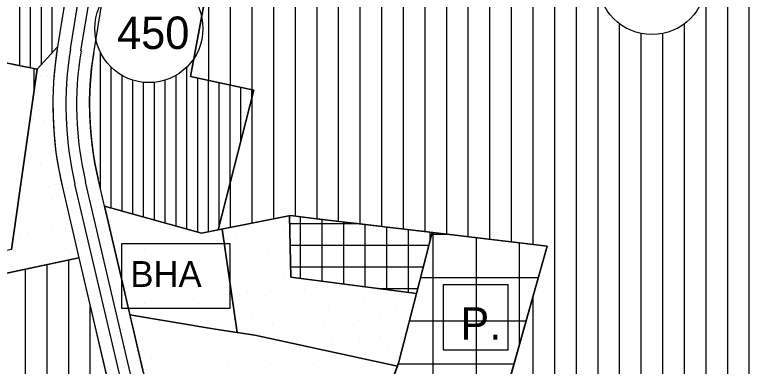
# Model space of a CAD drawing. Extents: x 419109 to 421295, y 4452223 to 4457798.
# Drawn here: x 420565 to 420904.9, y 4454003.1 to 4454165.8 of the extents above; entities that cross this region are included whole.
import ezdxf

# ---------------------------------------------------------------- set-up
doc = ezdxf.new("R2010")
doc.units = 0
for name, color, linetype in [('ADA', 7, 'Continuous'), ('ADAKENARI', 7, 'Continuous'), ('Default', 7, 'Continuous'), ('KALDIRIM', 7, 'Continuous'), ('LJ_SEMBOL', 7, 'Continuous'), ('PL_AYA_PARK_DINLENME', 7, 'Continuous'), ('PL_K_BHA', 7, 'Continuous'), ('PL_K_PAZAR_ALANI', 7, 'Continuous'), ('PL_K_TALI_IS_MRK', 7, 'Continuous'), ('PL_KON_MEV_350', 7, 'Continuous'), ('PL_KON_MEV_450', 7, 'Continuous'), ('PL_OZEL_DONATI', 7, 'Continuous'), ('SM_DAIRE', 7, 'Continuous'), ('SM_TAKS', 7, 'Continuous'), ('TR_ORTAYOGUNKONUT', 7, 'Continuous'), ('TR_PARKALANI', 7, 'Continuous'), ('TR_PAZARLAMAAL', 7, 'Continuous'), ('TR_SAGLIKTESIS', 7, 'Continuous'), ('TR_TALIISMERK', 7, 'Continuous'), ('TR_YONETIMMERK', 7, 'Continuous'), ('TR_YUKSEKYOGUNKONUT', 7, 'Continuous')]:
    doc.layers.add(name, color=color, linetype=linetype)

# ---------------------------------------------------------------- blocks, each defined once
blk = doc.blocks.new('POINT_DISPLAY')
at = {"layer": 'Default'}
blk.add_line((0, 0), (0, 0), dxfattribs=at)

msp = doc.modelspace()

# ---------------------------------------------------------------- linework, layer by layer
at = {"layer": 'ADA'}
for p, q in [((420646.34, 4454137.24), (420659.27, 4454206.63)), ((420575.43, 4454140.51), (420584.82, 4454150.89)), ((420575.43, 4454140.51), (420552.34, 4454145.16)), ((420575.43, 4454140.51), (420563.47, 4454057.09)), ((420675.69, 4454130.86), (420646.34, 4454137.24)), ((420659.2, 4454066.25), (420675.69, 4454130.86)), ((420606.57, 4454077.19), (420651.48, 4454064.74)), ((420659.2, 4454066.25), (420692.66, 4454072.81)), ((420692.66, 4454072.81), (420704.57, 4454071.4)), ((420704.57, 4454071.4), (420761.09, 4454064.67)), ((420651.48, 4454064.74), (420659.2, 4454066.25)), ((420667.91, 4454018.78), (420660.92, 4454066.59)), ((420750.88, 4454036.79), (420758.11, 4454065.02)), ((420761.09, 4454064.67), (420811.35, 4454058.68)), ((420811.35, 4454058.68), (420787.88, 4453975.61)), ((420449.98, 4454022.67), (420594.69, 4454053.33))]:
    msp.add_line(p, q, dxfattribs=at)
for points in [[(420750.88, 4454036.79), (420692.77, 4454044.43), (420692.08, 4454072.7)], [(420742.08, 4454003.26), (420742.77, 4454005.15), (420750.88, 4454036.79)], [(420742.08, 4454003.26), (420676.14, 4454017.51), (420669.88, 4454018.47), (420657.7, 4454020.34), (420618.32, 4454026.98)], [(420738.6, 4453993.7), (420742.77, 4454005.15)]]:
    msp.add_lwpolyline(points, dxfattribs=at)
at = {"layer": 'ADAKENARI'}
for p, q in [((420623.09, 4454386.03), (420584.82, 4454150.89)), ((420601.6, 4454148.16), (420640.08, 4454384.64)), ((420606.57, 4454077.19), (420603.6, 4454089.87)), ((420587.04, 4454086), (420594.69, 4454053.33)), ((420615.47, 4454039.16), (420606.57, 4454077.19)), ((420594.69, 4454053.33), (420635.91, 4453877.22)), ((420623.71, 4454003.95), (420615.47, 4454039.16)), ((420642.06, 4453925.53), (420623.71, 4454003.95))]:
    msp.add_line(p, q, dxfattribs=at)
for radius in [167, 150]:
    msp.add_arc((420749.65, 4454124.06), radius, 170.7564, 193.1743, dxfattribs=at)
at = {"layer": 'KALDIRIM'}
for p, q in [((420590.74, 4454149.92), (420600.91, 4454212.42)), ((420595.67, 4454149.12), (420605.88, 4454211.86)), ((420619.82, 4453972.32), (420592.89, 4454087.37)), ((420624.73, 4453973.26), (420597.75, 4454088.51))]:
    msp.add_line(p, q, dxfattribs=at)
for radius in [161, 156]:
    msp.add_arc((420749.65, 4454124.06), radius, 170.7564, 193.1743, dxfattribs=at)
at = {"layer": 'LJ_SEMBOL'}
msp.add_lwpolyline([(420614.58, 4454059.92), (420664.58, 4454059.92), (420664.58, 4454029.92), (420614.58, 4454029.92), (420614.58, 4454059.92), (420664.58, 4454059.92)], dxfattribs=at)
msp.add_lwpolyline([(420763.3, 4454010.79), (420793.3, 4454010.79), (420793.3, 4454040.79), (420763.3, 4454040.79)], close=True, dxfattribs=at)
at = {"layer": 'PL_AYA_PARK_DINLENME'}
for points in [[(420563.47, 4454057.09), (420575.43, 4454140.51), (420584.82, 4454150.89), (420584.82, 4454150.89), (420583.7, 4454142.8), (420582.99, 4454134.66), (420582.67, 4454126.5), (420582.75, 4454118.33), (420583.23, 4454110.18), (420584.1, 4454102.06), (420585.38, 4454094), (420587.04, 4454086), (420594.69, 4454053.33), (420449.98, 4454022.67)], [(420742.08, 4454003.26), (420742.77, 4454005.15), (420750.88, 4454036.79), (420692.77, 4454044.43), (420692.08, 4454072.7), (420684.86, 4454071.28), (420674.86, 4454069.32), (420664.86, 4454067.36), (420660.92, 4454066.59), (420667.91, 4454018.78), (420669.88, 4454018.47), (420676.14, 4454017.51), (420742.08, 4454003.26)]]:
    msp.add_lwpolyline(points, dxfattribs=at)
at = {"layer": 'PL_K_BHA'}
msp.add_lwpolyline([(420649.66, 4454065.24), (420644.66, 4454066.63), (420639.66, 4454068.02), (420634.66, 4454069.4), (420629.66, 4454070.79), (420624.66, 4454072.17), (420619.66, 4454073.56), (420614.66, 4454074.95), (420609.66, 4454076.33), (420606.57, 4454077.19), (420615.47, 4454039.16), (420618.32, 4454026.98), (420657.7, 4454020.34), (420667.91, 4454018.78), (420660.92, 4454066.59), (420659.2, 4454066.25), (420654.66, 4454065.37), (420651.48, 4454064.74), (420649.66, 4454065.24)], dxfattribs=at)
at = {"layer": 'PL_K_PAZAR_ALANI'}
msp.add_lwpolyline([(420804.86, 4454059.46), (420794.86, 4454060.65), (420784.86, 4454061.84), (420774.86, 4454063.03), (420764.86, 4454064.22), (420761.09, 4454064.67), (420758.11, 4454065.02), (420750.88, 4454036.79), (420742.77, 4454005.15), (420742.08, 4454003.26), (420738.6, 4453993.7), (420738.02, 4453990.72), (420745.54, 4453988.44), (420755.45, 4453985.44), (420787.88, 4453975.61), (420794.86, 4454000.31), (420804.86, 4454035.71), (420811.35, 4454058.68), (420804.86, 4454059.46)], dxfattribs=at)
at = {"layer": 'PL_K_TALI_IS_MRK'}
msp.add_lwpolyline([(420758.11, 4454065.02), (420754.86, 4454065.41), (420744.86, 4454066.6), (420734.86, 4454067.79), (420724.86, 4454068.98), (420714.86, 4454070.17), (420704.86, 4454071.36), (420704.57, 4454071.4), (420694.86, 4454072.55), (420692.66, 4454072.81), (420692.08, 4454072.7), (420692.77, 4454044.43), (420750.88, 4454036.79), (420758.11, 4454065.02)], dxfattribs=at)
at = {"layer": 'PL_KON_MEV_350'}
for points in [[(420474.73, 4454415.3), (420589.01, 4454400.52), (420552.34, 4454145.16), (420575.43, 4454140.51), (420563.47, 4454057.09), (420525.18, 4454049.57), (420441.81, 4454052.61), (420443.29, 4454073.24), (420452.08, 4454141.13), (420509.8, 4454133.33), (420520.05, 4454189.39), (420424.05, 4454204.21), (420426.46, 4454230.76), (420449.87, 4454228.36), (420493.48, 4454293.72), (420534.29, 4454288.28), (420537.28, 4454311.95), (420497.84, 4454316.84), (420493.48, 4454293.72), (420449.87, 4454228.36)], [(420491, 4453847.88), (420458.18, 4453987.01), (420449.98, 4454022.67), (420594.69, 4454053.33), (420635.91, 4453877.22)]]:
    msp.add_lwpolyline(points, close=True, dxfattribs=at)
msp.add_lwpolyline([(420787.88, 4453975.61), (420811.35, 4454058.68), (420761.09, 4454064.67), (420704.57, 4454071.4), (420692.66, 4454072.81), (420659.2, 4454066.25), (420675.69, 4454130.86), (420646.34, 4454137.24), (420659.27, 4454206.63)], dxfattribs=at)
at = {"layer": 'PL_KON_MEV_450'}
for points in [[(420575.43, 4454140.51), (420552.34, 4454145.16), (420589.01, 4454400.52), (420614.77, 4454397.18), (420623.09, 4454386.03), (420584.82, 4454150.89), (420584.82, 4454150.89)], [(420601.6, 4454148.16), (420640.08, 4454384.64), (420651.68, 4454394.92), (420664.91, 4454395.45), (420634.86, 4454213.81), (420659.27, 4454206.63), (420646.34, 4454137.24), (420675.69, 4454130.86), (420659.2, 4454066.25), (420651.48, 4454064.74), (420606.57, 4454077.19), (420603.6, 4454089.87), (420602.1, 4454097.06), (420600.96, 4454104.3), (420600.17, 4454111.59), (420599.74, 4454118.92), (420599.66, 4454126.25), (420599.95, 4454133.58), (420600.6, 4454140.89)]]:
    msp.add_lwpolyline(points, close=True, dxfattribs=at)
at = {"layer": 'PL_OZEL_DONATI'}
msp.add_lwpolyline([(420618.32, 4454026.98), (420623.71, 4454003.95), (420642.06, 4453925.53), (420642.67, 4453922.94), (420702.7, 4453941.9), (420714.74, 4453945.7), (420713.26, 4453950.4), (420714.55, 4453952.93), (420729.9, 4453957.83), (420732.17, 4453960.39), (420738.02, 4453990.72), (420738.6, 4453993.7), (420742.08, 4454003.26), (420676.14, 4454017.51), (420669.88, 4454018.47), (420667.91, 4454018.78), (420657.7, 4454020.34), (420618.32, 4454026.98)], dxfattribs=at)
at = {"layer": 'SM_DAIRE'}
for centre in [(420859.85, 4454181.58), (420627.09, 4454159.35)]:
    msp.add_circle(centre, 25, dxfattribs=at)
at = {"layer": 'TR_ORTAYOGUNKONUT'}
for p, q in [((420744.86, 4454066.6), (420744.86, 4454398.67)), ((420664.86, 4454133.22), (420664.86, 4454395.11)), ((420734.86, 4454067.79), (420734.86, 4454398.27)), ((420884.86, 4453954.97), (420884.86, 4454392.8)), ((420894.86, 4453952.55), (420894.86, 4454387.56)), ((420904.86, 4453950.13), (420904.86, 4454382.32)), ((420724.86, 4454068.98), (420724.86, 4454277.21)), ((420674.86, 4454069.32), (420674.86, 4454257.68)), ((420684.86, 4454071.28), (420684.86, 4454254.14)), ((420694.86, 4454072.55), (420694.86, 4454250.6)), ((420704.86, 4454071.36), (420704.86, 4454247.06)), ((420714.86, 4454070.17), (420714.86, 4454243.52)), ((420824.86, 4453940.39), (420824.86, 4454243.94)), ((420754.86, 4454065.41), (420754.86, 4454236.99)), ((420764.86, 4454064.22), (420764.86, 4454233.89)), ((420774.86, 4454063.03), (420774.86, 4454230.79)), ((420784.86, 4454061.84), (420784.86, 4454227.69)), ((420814.86, 4453942.58), (420814.86, 4454225.84)), ((420794.86, 4454060.65), (420794.86, 4454224.59)), ((420804.86, 4454059.46), (420804.86, 4454221.49)), ((420654.86, 4454135.39), (420654.86, 4454182.95)), ((420834.86, 4453938.19), (420834.86, 4454180.89)), ((420844.86, 4453936), (420844.86, 4454161.57)), ((420874.86, 4453957.38), (420874.86, 4454161.58)), ((420854.86, 4453961.89), (420854.86, 4454157.08)), ((420864.86, 4453959.8), (420864.86, 4454157.08)), ((420574.05, 4454130.84), (420574.05, 4454140.78)), ((420664.86, 4454067.36), (420664.86, 4454088.42)), ((420589.98, 4453867.92), (420589.98, 4454052.33)), ((420579.98, 4453865.89), (420579.98, 4454050.21)), ((420569.98, 4453863.87), (420569.98, 4454048.09)), ((420804.86, 4453944.78), (420804.86, 4454035.71)), ((420599.98, 4453869.94), (420599.98, 4454030.74))]:
    msp.add_line(p, q, dxfattribs=at)
at = {"layer": 'TR_PAZARLAMAAL'}
for p, q in [((420757.91, 4454064.23), (420764.73, 4454064.23)), ((420758.61, 4453984.48), (420758.61, 4454064.96)), ((420778.61, 4453978.42), (420778.61, 4454062.58)), ((420798.61, 4454013.6), (420798.61, 4454060.2)), ((420752.78, 4454044.23), (420807.26, 4454044.23)), ((420747.66, 4454024.23), (420801.61, 4454024.23)), ((420742.44, 4454004.23), (420795.96, 4454004.23))]:
    msp.add_line(p, q, dxfattribs=at)
at = {"layer": 'TR_TALIISMERK'}
for p, q in [((420697.21, 4454043.85), (420697.21, 4454072.27)), ((420692.16, 4454069.16), (420723.36, 4454069.16)), ((420707.21, 4454042.53), (420707.21, 4454071.08)), ((420717.21, 4454041.22), (420717.21, 4454069.89)), ((420727.21, 4454039.9), (420727.21, 4454068.7)), ((420737.21, 4454038.59), (420737.21, 4454067.51)), ((420747.21, 4454037.27), (420747.21, 4454066.32)), ((420757.21, 4454061.51), (420757.21, 4454065.13)), ((420692.41, 4454059.16), (420756.61, 4454059.16)), ((420692.65, 4454049.16), (420754.05, 4454049.16)), ((420732.87, 4454039.16), (420751.48, 4454039.16))]:
    msp.add_line(p, q, dxfattribs=at)
at = {"layer": 'TR_YUKSEKYOGUNKONUT'}
for p, q in [((420572.34, 4454141.13), (420572.34, 4454284.43)), ((420577.34, 4454142.62), (420577.34, 4454281.19)), ((420582.34, 4454148.15), (420582.34, 4454278.65)), ((420567.34, 4454142.14), (420567.34, 4454249.62)), ((420604.66, 4454085.31), (420604.66, 4454148.3)), ((420609.66, 4454076.33), (420609.66, 4454141.43)), ((420644.66, 4454066.63), (420644.66, 4454141.57)), ((420614.66, 4454074.95), (420614.66, 4454137.66)), ((420639.66, 4454068.02), (420639.66, 4454137.74)), ((420619.66, 4454073.56), (420619.66, 4454135.48)), ((420624.66, 4454072.17), (420624.66, 4454134.47)), ((420629.66, 4454070.79), (420629.66, 4454134.48)), ((420634.66, 4454069.4), (420634.66, 4454135.52)), ((420649.66, 4454065.24), (420649.66, 4454136.52)), ((420654.66, 4454065.37), (420654.66, 4454135.43)), ((420659.66, 4454068.08), (420659.66, 4454134.35)), ((420664.66, 4454087.67), (420664.66, 4454133.26)), ((420669.66, 4454107.26), (420669.66, 4454132.17)), ((420674.66, 4454126.84), (420674.66, 4454131.08))]:
    msp.add_line(p, q, dxfattribs=at)

# ---------------------------------------------------------------- block references
at = {"layer": 'TR_PARKALANI', "xscale": 0.1, "yscale": 0.10000000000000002}
for p in [(420576.82, 4454137.22), (420579.67, 4454137.37), (420576.51, 4454121.56), (420573.35, 4454117.52), (420578.22, 4454116.81), (420570.74, 4454102.75), (420576.77, 4454096.25), (420584.65, 4454095.22), (420583.43, 4454087.27), (420568.66, 4454084.66), (420580.48, 4454085.73), (420582.04, 4454080.45), (420575.32, 4454075.68), (420679.84, 4454070.07), (420581.98, 4454066.7), (420689.67, 4454067.32), (420567.21, 4454064.1), (420571.58, 4454065.21), (420667.8, 4454063.37), (420792.02, 4454060.91), (420577.7, 4454055.83), (420588.64, 4454057.72), (420593.34, 4454058.15), (420681.77, 4454056.24), (420573.87, 4454055.12), (420671.6, 4454048.91), (420689.67, 4454045.61), (420807.92, 4454046.81), (420699.08, 4454038.62), (420714.11, 4454038.62), (420672.66, 4454037.26), (420681.01, 4454035.85), (420746, 4454036.04), (420726.87, 4454033.12), (420690.12, 4454027.99), (420710.16, 4454030.88), (420741.75, 4454029.21), (420674.94, 4454027.04), (420734.31, 4454025.26), (420684.5, 4454022.98), (420708.04, 4454021.58), (420724.13, 4454024.31), (420694.07, 4454016.91), (420711.99, 4454015.2), (420724.29, 4454016.15), (420733.55, 4454016.91), (420737.8, 4454012.35)]:
    msp.add_blockref('POINT_DISPLAY', p, dxfattribs=at)
at = {"layer": 'TR_SAGLIKTESIS', "xscale": 0.1, "yscale": 0.10000000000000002}
for p in [(420628.35, 4454006.66), (420643.81, 4454005.55), (420663.81, 4454005.55), (420683.34, 4454004.48), (420703.34, 4454004.48)]:
    msp.add_blockref('POINT_DISPLAY', p, dxfattribs=at)
at = {"layer": 'TR_YONETIMMERK', "xscale": 0.1, "yscale": 0.10000000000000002}
for p in [(420625.21, 4454057.18), (420650.21, 4454057.18), (420625.21, 4454032.18), (420650.21, 4454032.18)]:
    msp.add_blockref('POINT_DISPLAY', p, dxfattribs=at)

# ---------------------------------------------------------------- texts
at = {"layer": 'LJ_SEMBOL'}
for s, height, p in [('BHA', 12, (420618.5, 4454039.81)), ('P.', 15, (420771.16, 4454015.42))]:
    msp.add_text(s, height=height, dxfattribs=at).set_placement(p)
at = {"layer": 'SM_TAKS'}
msp.add_text('450', height=15, dxfattribs=at).set_placement((420612.35, 4454149.91))

doc.saveas('drawing.dxf')
